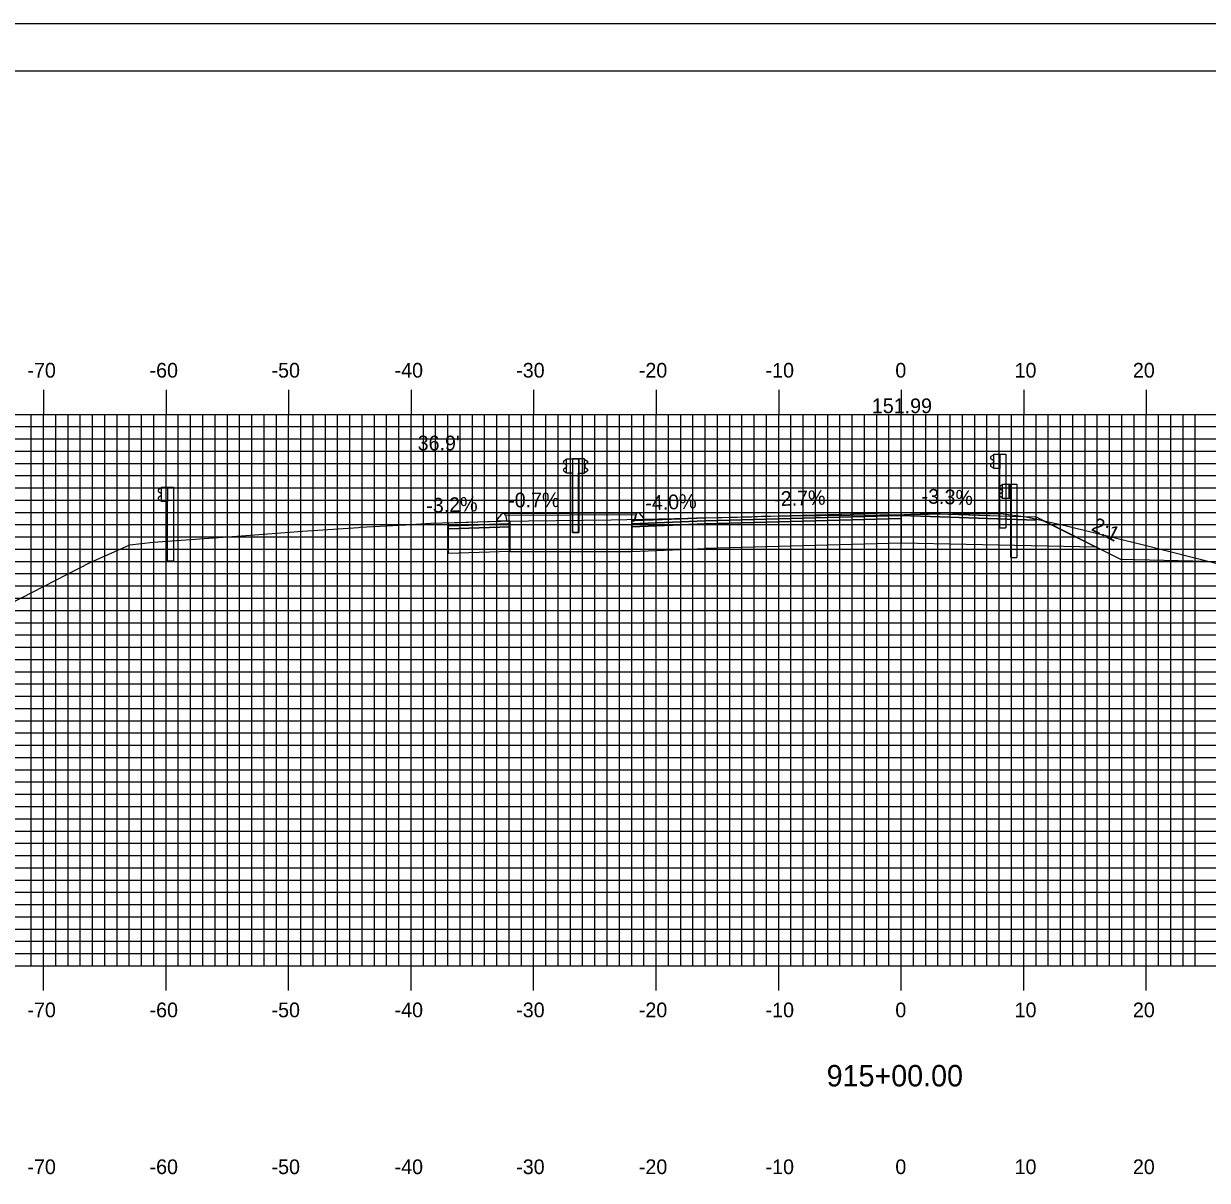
# Model space of a CAD drawing. Extents: x 860652 to 860995, y 364765 to 364985.
# Drawn here: x 860745.8 to 860842.4, y 364890.8 to 364985.2 of the extents above; entities that cross this region are included whole.
import ezdxf

# ---------------------------------------------------------------- set-up
doc = ezdxf.new("R2010")
doc.units = 0
for name, color, linetype in [('ANNOTATION', 7, 'Continuous'), ('BORDER', 7, 'Continuous'), ('D_Curb_Type_3M2_Lt', 7, 'Continuous'), ('D_Curb_Type_3M2_Rt', 7, 'Continuous'), ('D_Guardrail_Beam_Rt', 7, 'Continuous'), ('D_Roadway_Centerline', 7, 'Continuous'), ('D_Roadway_Centerline_Text', 7, 'Continuous'), ('D_Roadway_Edge_Shoulder', 7, 'Continuous'), ('D_Roadway_Edge_TW', 7, 'Continuous'), ('D_Roadway_FinishedGrade', 7, 'Continuous'), ('D_Roadway_Pavement', 7, 'Continuous'), ('D_Roadway_SlopeLines', 7, 'Continuous'), ('D_Roadway_SubGrade', 7, 'Continuous'), ('D_Text_Standard', 7, 'Continuous'), ('H_V ANNOTATION', 7, 'Continuous'), ('M_Guardrail', 7, 'Continuous'), ('M_Roadway_Centerline', 7, 'Continuous'), ('MAJOR', 7, 'Continuous'), ('MINOR', 7, 'Continuous'), ('PLOT BOUNDARY', 7, 'Continuous'), ('S_Roadway_Centerline', 7, 'Continuous')]:
    doc.layers.add(name, color=color, linetype=linetype)

msp = doc.modelspace()

# ---------------------------------------------------------------- linework, layer by layer
at = {"layer": 'BORDER'}
msp.add_lwpolyline([(860667.812, 364771.302), (860987.812, 364771.302), (860987.812, 364981.302), (860667.812, 364981.302)], close=True, dxfattribs=at)
at = {"layer": 'D_Curb_Type_3M2_Lt'}
for p, q in [((860795.906, 364945.28), (860795.911, 364945.28)), ((860796.412, 364944.824), (860796.058, 364945.226)), ((860795.77, 364945.151), (860795.662, 364944.657)), ((860795.662, 364944.657), (860796.412, 364944.657)), ((860796.412, 364944.657), (860796.412, 364944.824))]:
    msp.add_line(p, q, dxfattribs=at)
msp.add_arc((860795.933, 364945.116), 0.167, 41.38705, 167.66476, dxfattribs=at)
at = {"layer": 'D_Curb_Type_3M2_Rt'}
for p, q in [((860784.473, 364944.753), (860784.827, 364945.155)), ((860784.473, 364944.586), (860784.473, 364944.753)), ((860785.223, 364944.586), (860784.473, 364944.586)), ((860785.115, 364945.08), (860785.223, 364944.586))]:
    msp.add_line(p, q, dxfattribs=at)
msp.add_arc((860784.952, 364945.045), 0.167, 12.33524, 138.61295, dxfattribs=at)
at = {"layer": 'D_Guardrail_Beam_Rt'}
for p, q in [((860825.593, 364947.507), (860825.45, 364947.407)), ((860825.45, 364947.264), (860825.645, 364947.128)), ((860825.683, 364947.528), (860825.609, 364947.514)), ((860825.683, 364947.612), (860826.371, 364947.612)), ((860825.683, 364946.445), (860825.683, 364947.612)), ((860826.204, 364947.612), (860826.204, 364946.445)), ((860826.308, 364947.612), (860826.308, 364946.445)), ((860826.371, 364947.612), (860826.841, 364947.612)), ((860826.371, 364947.612), (860826.371, 364946.445)), ((860826.841, 364947.612), (860826.841, 364941.612)), ((860825.645, 364946.929), (860825.45, 364946.793)), ((860825.45, 364946.649), (860825.593, 364946.55)), ((860825.609, 364946.543), (860825.683, 364946.528)), ((860825.679, 364947.063), (860825.679, 364946.993)), ((860826.371, 364946.445), (860825.683, 364946.445)), ((860826.35, 364941.612), (860826.35, 364946.445)), ((860826.35, 364941.612), (860826.841, 364941.612))]:
    msp.add_line(p, q, dxfattribs=at)
for centre, major_axis, start_param, end_param in [((860825.5, 364947.335), (-0.0877, 0), 5.323254, 7.243116), ((860825.617, 364947.473), (-0.0417, 0), 4.907132, 5.323254), ((860825.6, 364947.063), (0.0789, 0), 0, 0.959931), ((860825.5, 364946.721), (-0.0877, 0), 5.323254, 7.243116), ((860825.617, 364946.583), (-0.0417, 0), 0.959931, 1.376053), ((860825.6, 364946.993), (0.0789, 0), 5.323254, 6.283185)]:
    msp.add_ellipse(centre, major_axis=major_axis, ratio=0.995501, start_param=start_param, end_param=end_param, dxfattribs=at)
at = {"layer": 'D_Roadway_Centerline'}
for p, q in [((860828.413, 364944.928), (860835.317, 364941.476)), ((860835.317, 364941.476), (860842.378, 364941.335))]:
    msp.add_line(p, q, dxfattribs=at)
for points in [[(860796.415, 364944.657), (860798.657, 364944.747), (860801.403, 364944.857), (860801.412, 364944.857), (860806.742, 364945.003), (860817.412, 364945.294), (860817.421, 364945.294), (860821.267, 364945.166), (860825.384, 364945.029), (860825.412, 364945.028), (860825.423, 364945.028), (860827.361, 364944.963), (860828.413, 364944.928), (860829.026, 364944.621), (860829.029, 364944.62), (860833.317, 364942.476)], [(860780.472, 364944.458), (860781.171, 364944.481), (860784.473, 364944.586)]]:
    msp.add_lwpolyline(points, dxfattribs=at)
at = {"layer": 'D_Roadway_Edge_Shoulder'}
for points in [[(860817.412, 364945.294), (860825.412, 364945.028), (860825.412, 364945.028), (860828.413, 364944.928), (860828.413, 364944.678), (860817.412, 364945.044)], [(860780.472, 364944.458), (860784.473, 364944.586), (860785.473, 364944.617), (860785.473, 364944.367), (860780.472, 364944.208)], [(860801.412, 364944.857), (860796.412, 364944.657), (860795.413, 364944.617), (860795.413, 364944.367), (860801.412, 364944.607)]]:
    msp.add_lwpolyline(points, close=True, dxfattribs=at)
at = {"layer": 'D_Roadway_Edge_TW'}
msp.add_lwpolyline([(860801.412, 364944.857), (860817.412, 364945.294), (860817.412, 364945.044), (860801.412, 364944.607)], close=True, dxfattribs=at)
at = {"layer": 'D_Roadway_FinishedGrade'}
msp.add_lwpolyline([(860784.994, 364945.206), (860795.891, 364945.277)], dxfattribs=at)
at = {"layer": 'D_Roadway_Pavement'}
for points in [[(860780.472, 364944.208), (860785.473, 364944.367), (860785.473, 364944.117), (860780.472, 364943.958)], [(860801.412, 364944.607), (860795.413, 364944.367), (860795.413, 364944.117), (860801.412, 364944.357)], [(860801.412, 364944.607), (860817.412, 364945.044), (860817.412, 364944.794), (860801.412, 364944.357)]]:
    msp.add_lwpolyline(points, close=True, dxfattribs=at)
msp.add_lwpolyline([(860817.412, 364945.044), (860817.412, 364944.794)], dxfattribs=at)
msp.add_lwpolyline([(860817.412, 364945.044), (860817.412, 364944.794)], dxfattribs=at)
at = {"layer": 'D_Roadway_SlopeLines'}
msp.add_lwpolyline([(860828.413, 364944.928), (860829.026, 364944.621)], dxfattribs=at)
at = {"layer": 'D_Roadway_SubGrade'}
for points in [[(860780.472, 364943.958), (860785.473, 364944.117), (860785.473, 364944.367), (860785.473, 364942.117), (860780.472, 364941.958)], [(860785.473, 364944.617), (860785.473, 364942.117), (860795.413, 364942.117), (860795.413, 364944.117), (860795.413, 364944.367), (860795.413, 364944.617), (860795.656, 364944.627), (860795.761, 364945.109), (860785.124, 364945.04), (860785.218, 364944.609)], [(860801.412, 364944.357), (860795.413, 364944.117), (860795.413, 364944.367), (860795.413, 364942.117), (860801.412, 364942.357)], [(860801.412, 364944.357), (860817.412, 364944.794), (860817.412, 364942.794), (860801.412, 364942.357)], [(860817.412, 364944.794), (860817.412, 364945.044), (860828.413, 364944.678), (860828.413, 364944.928), (860833.317, 364942.476), (860817.412, 364942.794)]]:
    msp.add_lwpolyline(points, close=True, dxfattribs=at)
at = {"layer": 'M_Guardrail'}
for p, q in [((860824.975, 364950.046), (860825.465, 364950.046)), ((860824.975, 364948.88), (860824.975, 364950.046)), ((860825.465, 364950.046), (860825.956, 364950.046)), ((860825.465, 364950.046), (860825.465, 364948.88)), ((860825.956, 364950.046), (860825.956, 364944.046)), ((860790.007, 364949.576), (860789.864, 364949.476)), ((860789.864, 364949.333), (860790.059, 364949.197)), ((860790.106, 364949.597), (860790.024, 364949.583)), ((860790.093, 364949.132), (860790.093, 364949.041)), ((860790.106, 364949.67), (860790.596, 364949.67)), ((860790.106, 364948.504), (860790.106, 364949.67)), ((860790.584, 364949.671), (860790.584, 364943.671)), ((860791.076, 364949.671), (860790.584, 364949.671)), ((860790.596, 364949.67), (860791.087, 364949.67)), ((860790.596, 364949.67), (860790.596, 364948.504)), ((860791.565, 364949.671), (860791.076, 364949.671)), ((860791.076, 364949.671), (860791.076, 364948.504)), ((860791.087, 364949.67), (860791.087, 364943.67)), ((860791.565, 364948.504), (860791.565, 364949.671)), ((860791.565, 364949.598), (860791.647, 364949.583)), ((860791.579, 364949.133), (860791.579, 364949.042)), ((860791.808, 364949.333), (860791.612, 364949.197)), ((860791.664, 364949.577), (860791.808, 364949.477)), ((860824.876, 364949.952), (860824.733, 364949.852)), ((860824.733, 364949.709), (860824.928, 364949.573)), ((860824.928, 364949.353), (860824.733, 364949.217)), ((860824.733, 364949.074), (860824.876, 364948.974)), ((860824.975, 364949.973), (860824.893, 364949.959)), ((860824.962, 364949.509), (860824.962, 364949.417)), ((860790.059, 364948.977), (860789.864, 364948.841)), ((860789.864, 364948.698), (860790.007, 364948.598)), ((860790.024, 364948.591), (860790.106, 364948.576)), ((860790.596, 364948.504), (860790.106, 364948.504)), ((860790.596, 364943.67), (860790.596, 364948.504)), ((860791.076, 364943.671), (860791.076, 364948.504)), ((860791.076, 364948.504), (860791.565, 364948.504)), ((860791.647, 364948.591), (860791.565, 364948.577)), ((860791.612, 364948.977), (860791.808, 364948.841)), ((860791.808, 364948.698), (860791.664, 364948.598)), ((860824.893, 364948.967), (860824.975, 364948.953)), ((860825.465, 364948.88), (860824.975, 364948.88)), ((860825.465, 364944.046), (860825.465, 364948.88)), ((860756.938, 364947.253), (860756.795, 364947.153)), ((860757.037, 364947.275), (860756.955, 364947.26)), ((860757.037, 364947.348), (860757.527, 364947.348)), ((860757.037, 364946.181), (860757.037, 364947.348)), ((860757.527, 364947.348), (860758.018, 364947.348)), ((860757.527, 364947.348), (860757.527, 364946.181)), ((860758.018, 364947.348), (860758.018, 364941.348)), ((860756.795, 364947.01), (860756.99, 364946.874)), ((860756.99, 364946.654), (860756.795, 364946.518)), ((860756.795, 364946.375), (860756.938, 364946.275)), ((860756.955, 364946.268), (860757.037, 364946.254)), ((860757.024, 364946.81), (860757.024, 364946.719)), ((860757.527, 364946.181), (860757.037, 364946.181)), ((860757.527, 364941.348), (860757.527, 364946.181)), ((860791.076, 364943.671), (860790.584, 364943.671)), ((860790.596, 364943.67), (860791.087, 364943.67)), ((860825.465, 364944.046), (860825.956, 364944.046)), ((860757.527, 364941.348), (860758.018, 364941.348))]:
    msp.add_line(p, q, dxfattribs=at)
for centre, major_axis, start_param, end_param in [((860789.914, 364949.404), (-0.0877, 0), 5.323254, 7.243116), ((860790.031, 364949.542), (-0.0417, 0), 4.886922, 5.323254), ((860790.014, 364949.132), (0.0789, 0), 0, 0.959931), ((860791.658, 364949.133), (-0.0789, 0), 5.323254, 6.283185), ((860791.64, 364949.543), (0.0417, 0), 0.959931, 1.396263), ((860791.757, 364949.405), (0.0877, 0), 5.323254, 7.243116), ((860824.783, 364949.781), (-0.0877, 0), 5.323254, 7.243116), ((860824.783, 364949.145), (-0.0877, 0), 5.323254, 7.243116), ((860824.9, 364949.918), (-0.0417, 0), 4.886922, 5.323254), ((860824.883, 364949.509), (0.0789, 0), 0, 0.959931), ((860824.883, 364949.417), (0.0789, 0), 5.323254, 6.283185), ((860789.914, 364948.769), (-0.0877, 0), 5.323254, 7.243116), ((860790.031, 364948.632), (-0.0417, 0), 0.959931, 1.396263), ((860790.014, 364949.041), (0.0789, 0), 5.323254, 6.283185), ((860791.658, 364949.042), (-0.0789, 0), 6.283185, 7.243116), ((860791.64, 364948.632), (0.0417, 0), 4.886922, 5.323254), ((860791.757, 364948.77), (0.0877, 0), 5.323254, 7.243116), ((860824.9, 364949.008), (-0.0417, 0), 0.959931, 1.396263), ((860756.845, 364947.082), (-0.0877, 0), 5.323254, 7.243116), ((860756.962, 364947.219), (-0.0417, 0), 4.886922, 5.323254), ((860756.845, 364946.447), (-0.0877, 0), 5.323254, 7.243116), ((860756.962, 364946.309), (-0.0417, 0), 0.959931, 1.396263), ((860756.945, 364946.81), (0.0789, 0), 0, 0.959931), ((860756.945, 364946.719), (0.0789, 0), 5.323254, 6.283185)]:
    msp.add_ellipse(centre, major_axis=major_axis, ratio=0.995501, start_param=start_param, end_param=end_param, dxfattribs=at)
at = {"layer": 'MAJOR'}
for p, q in [((860747.412, 364955.306), (860747.412, 364953.302)), ((860757.412, 364955.306), (860757.412, 364953.302)), ((860767.412, 364955.306), (860767.412, 364953.302)), ((860777.412, 364955.306), (860777.412, 364953.302)), ((860787.412, 364955.306), (860787.412, 364953.302)), ((860797.412, 364955.306), (860797.412, 364953.302)), ((860807.412, 364955.306), (860807.412, 364953.302)), ((860817.412, 364955.306), (860817.412, 364953.302)), ((860827.412, 364955.306), (860827.412, 364953.302)), ((860837.412, 364955.306), (860837.412, 364953.302)), ((860677.412, 364953.302), (860957.412, 364953.302)), ((860677.412, 364953.302), (860957.412, 364953.302)), ((860747.412, 364908.302), (860747.412, 364953.302)), ((860757.412, 364908.302), (860757.412, 364953.302)), ((860767.412, 364908.302), (860767.412, 364953.302)), ((860777.412, 364908.302), (860777.412, 364953.302)), ((860787.412, 364908.302), (860787.412, 364953.302)), ((860797.412, 364908.302), (860797.412, 364953.302)), ((860807.412, 364908.302), (860807.412, 364953.302)), ((860817.412, 364908.302), (860817.412, 364953.302)), ((860827.412, 364908.302), (860827.412, 364953.302)), ((860837.412, 364908.302), (860837.412, 364953.302)), ((860677.412, 364948.302), (860957.412, 364948.302)), ((860677.412, 364943.302), (860957.412, 364943.302)), ((860677.412, 364938.302), (860957.412, 364938.302)), ((860677.412, 364933.302), (860957.412, 364933.302)), ((860677.412, 364928.302), (860957.412, 364928.302)), ((860677.412, 364923.302), (860957.412, 364923.302)), ((860677.412, 364918.302), (860957.412, 364918.302)), ((860677.412, 364913.302), (860957.412, 364913.302)), ((860677.412, 364908.302), (860957.412, 364908.302)), ((860677.412, 364908.302), (860957.412, 364908.302)), ((860747.412, 364906.298), (860747.412, 364908.302)), ((860757.412, 364906.298), (860757.412, 364908.302)), ((860767.412, 364906.298), (860767.412, 364908.302)), ((860777.412, 364906.298), (860777.412, 364908.302)), ((860787.412, 364906.298), (860787.412, 364908.302)), ((860797.412, 364906.298), (860797.412, 364908.302)), ((860807.412, 364906.298), (860807.412, 364908.302)), ((860817.412, 364906.298), (860817.412, 364908.302)), ((860827.412, 364906.298), (860827.412, 364908.302)), ((860837.412, 364906.298), (860837.412, 364908.302))]:
    msp.add_line(p, q, dxfattribs=at)
at = {"layer": 'MINOR'}
for p, q in [((860746.412, 364908.302), (860746.412, 364953.302)), ((860748.412, 364908.302), (860748.412, 364953.302)), ((860749.412, 364908.302), (860749.412, 364953.302)), ((860750.412, 364908.302), (860750.412, 364953.302)), ((860751.412, 364908.302), (860751.412, 364953.302)), ((860752.412, 364908.302), (860752.412, 364953.302)), ((860753.412, 364908.302), (860753.412, 364953.302)), ((860754.412, 364908.302), (860754.412, 364953.302)), ((860755.412, 364908.302), (860755.412, 364953.302)), ((860756.412, 364908.302), (860756.412, 364953.302)), ((860758.412, 364908.302), (860758.412, 364953.302)), ((860759.412, 364908.302), (860759.412, 364953.302)), ((860760.412, 364908.302), (860760.412, 364953.302)), ((860761.412, 364908.302), (860761.412, 364953.302)), ((860762.412, 364908.302), (860762.412, 364953.302)), ((860763.412, 364908.302), (860763.412, 364953.302)), ((860764.412, 364908.302), (860764.412, 364953.302)), ((860765.412, 364908.302), (860765.412, 364953.302)), ((860766.412, 364908.302), (860766.412, 364953.302)), ((860768.412, 364908.302), (860768.412, 364953.302)), ((860769.412, 364908.302), (860769.412, 364953.302)), ((860770.412, 364908.302), (860770.412, 364953.302)), ((860771.412, 364908.302), (860771.412, 364953.302)), ((860772.412, 364908.302), (860772.412, 364953.302)), ((860773.412, 364908.302), (860773.412, 364953.302)), ((860774.412, 364908.302), (860774.412, 364953.302)), ((860775.412, 364908.302), (860775.412, 364953.302)), ((860776.412, 364908.302), (860776.412, 364953.302)), ((860778.412, 364908.302), (860778.412, 364953.302)), ((860779.412, 364908.302), (860779.412, 364953.302)), ((860780.412, 364908.302), (860780.412, 364953.302)), ((860781.412, 364908.302), (860781.412, 364953.302)), ((860782.412, 364908.302), (860782.412, 364953.302)), ((860783.412, 364908.302), (860783.412, 364953.302)), ((860784.412, 364908.302), (860784.412, 364953.302)), ((860785.412, 364908.302), (860785.412, 364953.302)), ((860786.412, 364908.302), (860786.412, 364953.302)), ((860788.412, 364908.302), (860788.412, 364953.302)), ((860789.412, 364908.302), (860789.412, 364953.302)), ((860790.412, 364908.302), (860790.412, 364953.302)), ((860791.412, 364908.302), (860791.412, 364953.302)), ((860792.412, 364908.302), (860792.412, 364953.302)), ((860793.412, 364908.302), (860793.412, 364953.302)), ((860794.412, 364908.302), (860794.412, 364953.302)), ((860795.412, 364908.302), (860795.412, 364953.302)), ((860796.412, 364908.302), (860796.412, 364953.302)), ((860798.412, 364908.302), (860798.412, 364953.302)), ((860799.412, 364908.302), (860799.412, 364953.302)), ((860800.412, 364908.302), (860800.412, 364953.302)), ((860801.412, 364908.302), (860801.412, 364953.302)), ((860802.412, 364908.302), (860802.412, 364953.302)), ((860803.412, 364908.302), (860803.412, 364953.302)), ((860804.412, 364908.302), (860804.412, 364953.302)), ((860805.412, 364908.302), (860805.412, 364953.302)), ((860806.412, 364908.302), (860806.412, 364953.302)), ((860808.412, 364908.302), (860808.412, 364953.302)), ((860809.412, 364908.302), (860809.412, 364953.302)), ((860810.412, 364908.302), (860810.412, 364953.302)), ((860811.412, 364908.302), (860811.412, 364953.302)), ((860812.412, 364908.302), (860812.412, 364953.302)), ((860813.412, 364908.302), (860813.412, 364953.302)), ((860814.412, 364908.302), (860814.412, 364953.302)), ((860815.412, 364908.302), (860815.412, 364953.302)), ((860816.412, 364908.302), (860816.412, 364953.302)), ((860818.412, 364908.302), (860818.412, 364953.302)), ((860819.412, 364908.302), (860819.412, 364953.302)), ((860820.412, 364908.302), (860820.412, 364953.302)), ((860821.412, 364908.302), (860821.412, 364953.302)), ((860822.412, 364908.302), (860822.412, 364953.302)), ((860823.412, 364908.302), (860823.412, 364953.302)), ((860824.412, 364908.302), (860824.412, 364953.302)), ((860825.412, 364908.302), (860825.412, 364953.302)), ((860826.412, 364908.302), (860826.412, 364953.302)), ((860828.412, 364908.302), (860828.412, 364953.302)), ((860829.412, 364908.302), (860829.412, 364953.302)), ((860830.412, 364908.302), (860830.412, 364953.302)), ((860831.412, 364908.302), (860831.412, 364953.302)), ((860832.412, 364908.302), (860832.412, 364953.302)), ((860833.412, 364908.302), (860833.412, 364953.302)), ((860834.412, 364908.302), (860834.412, 364953.302)), ((860835.412, 364908.302), (860835.412, 364953.302)), ((860836.412, 364908.302), (860836.412, 364953.302)), ((860838.412, 364908.302), (860838.412, 364953.302)), ((860839.412, 364908.302), (860839.412, 364953.302)), ((860840.412, 364908.302), (860840.412, 364953.302)), ((860841.412, 364908.302), (860841.412, 364953.302)), ((860677.412, 364952.302), (860957.412, 364952.302)), ((860677.412, 364951.302), (860957.412, 364951.302)), ((860677.412, 364950.302), (860957.412, 364950.302)), ((860677.412, 364949.302), (860957.412, 364949.302)), ((860677.412, 364947.302), (860957.412, 364947.302)), ((860677.412, 364946.302), (860957.412, 364946.302)), ((860677.412, 364945.302), (860957.412, 364945.302)), ((860677.412, 364944.302), (860957.412, 364944.302)), ((860677.412, 364942.302), (860957.412, 364942.302)), ((860677.412, 364941.302), (860957.412, 364941.302)), ((860677.412, 364940.302), (860957.412, 364940.302)), ((860677.412, 364939.302), (860957.412, 364939.302)), ((860677.412, 364937.302), (860957.412, 364937.302)), ((860677.412, 364936.302), (860957.412, 364936.302)), ((860677.412, 364935.302), (860957.412, 364935.302)), ((860677.412, 364934.302), (860957.412, 364934.302)), ((860677.412, 364932.302), (860957.412, 364932.302)), ((860677.412, 364931.302), (860957.412, 364931.302)), ((860677.412, 364930.302), (860957.412, 364930.302)), ((860677.412, 364929.302), (860957.412, 364929.302)), ((860677.412, 364927.302), (860957.412, 364927.302)), ((860677.412, 364926.302), (860957.412, 364926.302)), ((860677.412, 364925.302), (860957.412, 364925.302)), ((860677.412, 364924.302), (860957.412, 364924.302)), ((860677.412, 364922.302), (860957.412, 364922.302)), ((860677.412, 364921.302), (860957.412, 364921.302)), ((860677.412, 364920.302), (860957.412, 364920.302)), ((860677.412, 364919.302), (860957.412, 364919.302)), ((860677.412, 364917.302), (860957.412, 364917.302)), ((860677.412, 364916.302), (860957.412, 364916.302)), ((860677.412, 364915.302), (860957.412, 364915.302)), ((860677.412, 364914.302), (860957.412, 364914.302)), ((860677.412, 364912.302), (860957.412, 364912.302)), ((860677.412, 364911.302), (860957.412, 364911.302)), ((860677.412, 364910.302), (860957.412, 364910.302)), ((860677.412, 364909.302), (860957.412, 364909.302))]:
    msp.add_line(p, q, dxfattribs=at)
at = {"layer": 'PLOT BOUNDARY'}
msp.add_lwpolyline([(860651.626, 364765.184), (860991.626, 364765.184), (860991.626, 364985.184), (860651.626, 364985.184)], close=True, dxfattribs=at)
at = {"layer": 'S_Roadway_Centerline'}
msp.add_lwpolyline([(860736.114, 364933.449), (860751.219, 364941.215), (860754.454, 364942.665), (860756.363, 364942.866), (860763.564, 364943.396), (860768.537, 364943.781), (860773.104, 364944.065), (860773.263, 364944.094), (860776.986, 364944.297), (860779.031, 364944.412), (860784.721, 364944.594), (860793.737, 364944.701), (860804.062, 364944.916), (860805.193, 364944.948), (860805.999, 364944.983), (860815.654, 364945.104), (860823.578, 364945.206), (860825.525, 364945.215), (860827.596, 364944.945), (860830.899, 364944.197), (860837.07, 364942.669), (860847.483, 364940.052)], dxfattribs=at)

# ---------------------------------------------------------------- texts
at = {"layer": 'ANNOTATION'}
for s, rotation, p in [('-2.7%', 1.56449, (860807.058, 364945.812)), ('-3.3%', 358.09575, (860819.052, 364946.041)), ('-3.2%', 1.82771, (860778.661, 364945.256)), ('-0.7%', 0.39389, (860785.336, 364945.706)), ('-4.0%', 2.29089, (860796.541, 364945.464)), ('2:1', 333.44325, (860832.851, 364943.876))]:
    msp.add_text(s, height=1.2, rotation=rotation, dxfattribs=at).set_placement(p)
at = {"layer": 'D_Roadway_Centerline_Text'}
msp.add_text('151.99', height=1.2, dxfattribs=at).set_placement((860815.015, 364953.399))
at = {"layer": 'D_Text_Standard'}
msp.add_text("36.9'", height=1.2, dxfattribs=at).set_placement((860777.944, 364950.363))
at = {"layer": 'H_V ANNOTATION'}
for s, height, p in [('-70', 1.2, (860746.096, 364956.302)), ('-60', 1.2, (860756.064, 364956.302)), ('-50', 1.2, (860766.021, 364956.302)), ('-40', 1.2, (860776.064, 364956.302)), ('-30', 1.2, (860785.989, 364956.302)), ('-20', 1.2, (860795.999, 364956.302)), ('-10', 1.2, (860806.342, 364956.302)), ('0', 1.2, (860816.931, 364956.302)), ('10', 1.2, (860826.663, 364956.302)), ('20', 1.2, (860836.32, 364956.302)), ('-70', 1.2, (860746.096, 364904.102)), ('-60', 1.2, (860756.064, 364904.102)), ('-50', 1.2, (860766.021, 364904.102)), ('-40', 1.2, (860776.064, 364904.102)), ('-30', 1.2, (860785.989, 364904.102)), ('-20', 1.2, (860795.999, 364904.102)), ('-10', 1.2, (860806.342, 364904.102)), ('0', 1.2, (860816.931, 364904.102)), ('10', 1.2, (860826.663, 364904.102)), ('20', 1.2, (860836.32, 364904.102)), ('915+00.00', 1.75, (860811.326, 364898.458)), ('-70', 1.2, (860746.096, 364891.302)), ('-60', 1.2, (860756.064, 364891.302)), ('-50', 1.2, (860766.021, 364891.302)), ('-40', 1.2, (860776.064, 364891.302)), ('-30', 1.2, (860785.989, 364891.302)), ('-20', 1.2, (860795.999, 364891.302)), ('-10', 1.2, (860806.342, 364891.302)), ('0', 1.2, (860816.931, 364891.302)), ('10', 1.2, (860826.663, 364891.302)), ('20', 1.2, (860836.32, 364891.302))]:
    msp.add_text(s, height=height, dxfattribs=at).set_placement(p)
at = {"layer": 'M_Roadway_Centerline'}
for s, p in [('C', (860805.994, 364944.983)), ('L', (860805.999, 364944.976)), ('C', (860773.257, 364944.094)), ('L', (860773.263, 364944.087))]:
    msp.add_text(s, height=0.0146, dxfattribs=at).set_placement(p)

doc.saveas('drawing.dxf')
